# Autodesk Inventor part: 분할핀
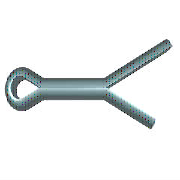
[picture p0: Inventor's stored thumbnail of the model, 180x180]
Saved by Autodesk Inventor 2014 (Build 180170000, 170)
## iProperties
IsCustomPart: 1
Created: 2012-02
Part Number: 분할핀
Material: 강철
Description: 분할 핀
Document SubType Name: Modeling
Standard: ISO 1234
Designer: mdu-01
Standard Revision: Second edition 1997-11-01
Standards Organization: ISO
Language: ko-KR
Size Designation: 2 x 14
Categories: <MemberInstance><Categories><Category DisplayName="조임쇠" InternalName="e4da775c-781d-43d5-af7c-5136215cf5a6" Mnemonic="FSTN"><Category DisplayName="핀" InternalNa
Density: 7.85 g/cm^3
Appearance: 파란색 - 벽 페인트 - 광택
Author: mdu-01
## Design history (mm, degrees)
sketch "스케치1"
  geometry: L1 (0, 0.9)-(8, 0.9); L2 (0, -0.9)-(8, -0.9); L3 (8, 0.9)-(14, 3.199); L4 (14, 3.199)-(14.301, 2.414); L5 (14.301, 2.414)-(8, 0); L6 (8, 0)-(16.801, -3.372); L7 (16.801, -3.372)-(16.5, -4.157); L8 (16.5, -4.157)-(8, -0.9); L9 (0, 0)-(-1.832, -0.821); L10 (0, 0)-(-1.832, 0.821); L11 (0, 0.9)-(0, -0.9); L12 (0, 0.9)-(-1.384, 1.604); L13 (0, -0.9)-(-1.384, -1.604); L14 (-4, 0)-(8, 0); L15 (8, 0.9)-(8, -0.9); A1 r 1.8 centre (-2.2, 0) between (-1.384, 1.604) and (-1.384, -1.604); A2 r 0.9 centre (-2.2, 0) between (-1.832, 0.821) and (-1.832, -0.821); 1 further point
  constraints: 30 end point, 5 point on circle, 4 parallel, 4 perpendicular, 4 point on line, 4 tangent, 2 centre point, 2 midpoint, 1 coincident, 1 horizontal
  dimensions: "d0" = 8 distance of L1.start L1.end (= MSIAB); "d1" = 14 horizontal distance of L1.start L3.end (= SNLG); "d2" = 159.037 deg angle of L1 L3; "d3" = 159.037 deg angle of L2 L8; "d4" = 2.5 horizontal distance of L3.end L7.end (= LGDIF); "d5" = 0.9 radius of A2 (= -0.5 x SNND1 + 0.5 x KBR); "d6" = 1.8 radius of A1 (= 0.5 x KBR); "d7" = 0.9 distance from line of L1 L9.start (= 0.5 x SNND1); "d8" = 0.9 distance between parallel lines of L2 L14 (= 0.5 x SNND1); "d9" = 2.2 distance from line of L11 A1.centre (= KOL - 0.5 x KBR)
extrude "본체" new body sketch "스케치1" stored distance "d10" = 1.8 (= SNND1); taper "d11" = 0 deg
workaxis "Work Axis1"
workplane "Work Plane1"
body "Solid1"
fillet "모깎기" dims "d12" = 0.72 (= 0.4 x SNND1)
node "작업 평면2"
other parameters: "SNND" = 2 [user parameter], "SNLG" = 14 [user parameter; used in 1 equation term], "SNND1" = 1.8 [user parameter; used in 5 equation terms], "KBR" = 3.6 [user parameter; used in 3 equation terms], "KOL" = 4 [user parameter; used in 1 equation term], "LGDIF" = 2.5 [user parameter; used in 1 equation term], "MSIAB" = 8 [user parameter; used in 1 equation term], "d15" = 0, "d16" = 0, "d17" = 0, "NNDMAX" = 9 [user parameter], "DSH" = 4 [user parameter], "NNDMIN" = 7 [user parameter]
